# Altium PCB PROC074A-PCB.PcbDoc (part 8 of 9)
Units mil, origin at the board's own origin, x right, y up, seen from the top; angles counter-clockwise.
Board outline 2755.91 x 5300 mil, 10 copper layers (Top Layer, L2-GND, L3-SIG1, L4-GND, L5-PWR/SIG, L6-SIG2, L7-PWR2, L8-SIG3, L9-GND, Bottom Layer), stack 67.57 mil thick; 585 components, 490 nets, 2137 pads, 1150 vias.
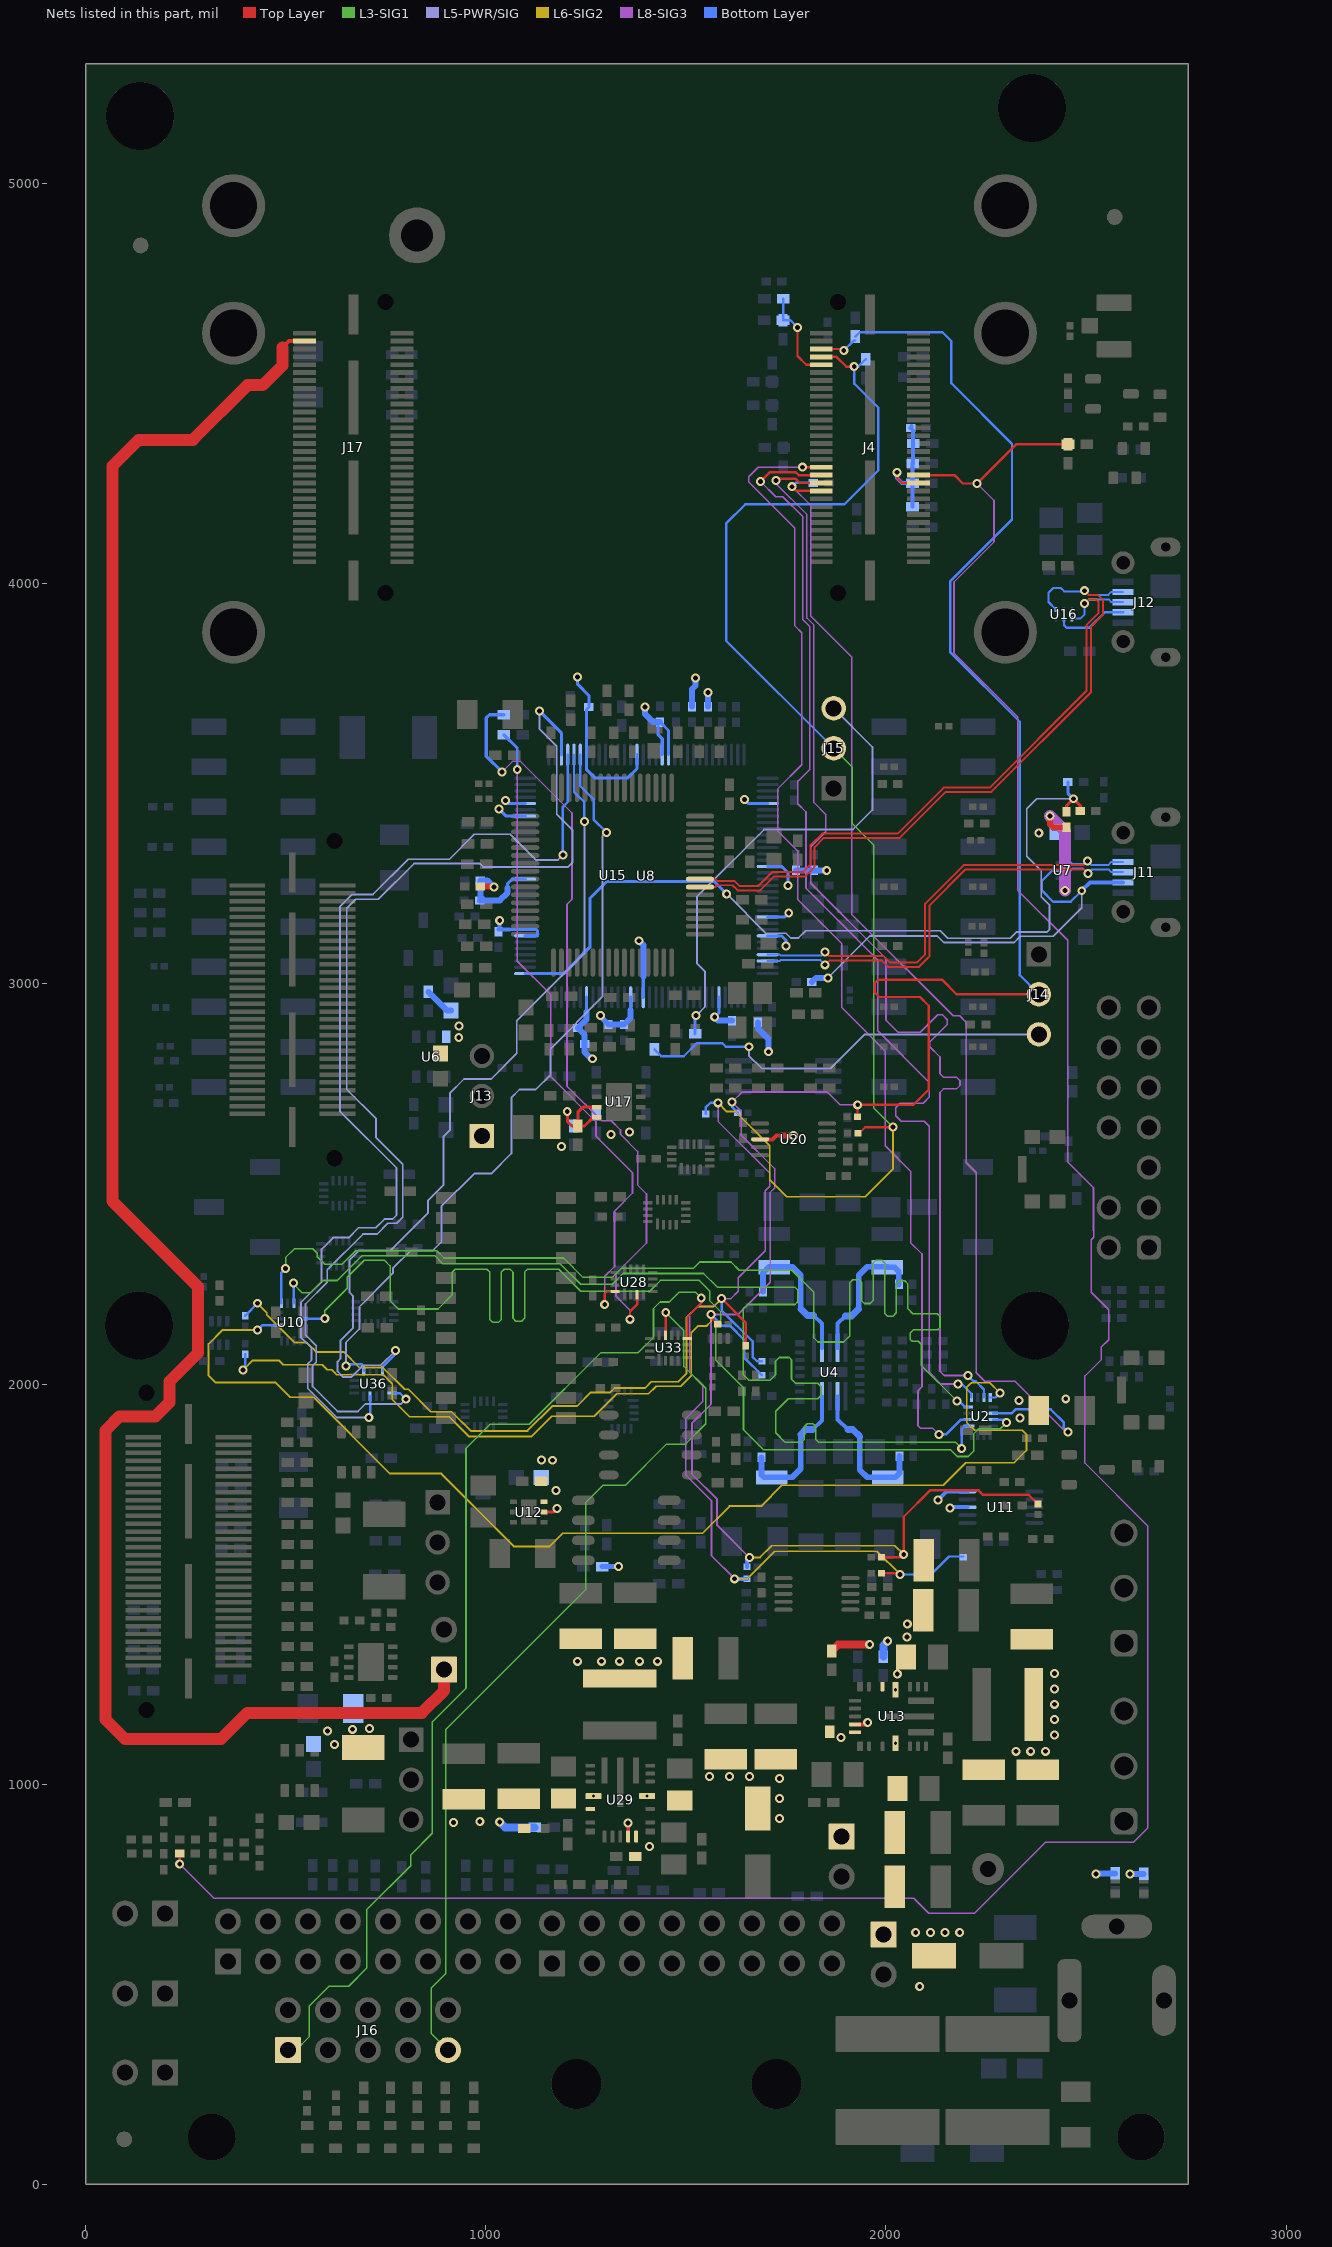
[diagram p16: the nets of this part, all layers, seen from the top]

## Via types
v1: diameter 22.4, hole 12.2, Top Layer to Bottom Layer, tented both sides, 1123 vias
v2: diameter 15.75, hole 7.87, Top Layer to Bottom Layer, tented both sides, 14 vias
v3: diameter 19.68, hole 7.87, Top Layer to Bottom Layer, tented both sides, 13 vias

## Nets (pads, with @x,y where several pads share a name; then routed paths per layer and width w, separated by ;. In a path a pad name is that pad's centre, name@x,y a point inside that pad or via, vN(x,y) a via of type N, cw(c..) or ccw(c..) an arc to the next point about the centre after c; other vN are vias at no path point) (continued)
RADAR_SCL: J4.55 J14.2 R9.1 R100.2 R171.1 R173.1 R303.2 R304.2 R319.2 R320.2 R321.2 | length 7706.2
  Top Layer w6: v1(1562.62,2173.53) 1562.62,2166.43 R173.1@1579.68,2149.37 ; J4.55@1838.5,4587.15 1890.48,4587.15 v1(1894.63,4583) ; R304.2@1928.9,2668.35 1928.9,2697.58 v1(1929.37,2698.06) 2068.87,2698.06 2106.89,2736.08 2106.89,2945.64 2085.15,2967.38 1983.39,2967.38 1971.82,2978.95 1971.82,3002.07 1980.61,3010.86 2140.02,3010.86 2176.82,2974.06 J14.2@2382.37,2974.06 ; R321.2@1989.09,1566.69 2037.01,1566.69 v1(2044.37,1574.06) 2044.37,1668.37 2110.28,1734.28 2231.72,1734.28 2243,1723 2357,1723 R303.2@2380,1700
  L6-SIG2 w4.5: v1(393.37,2035.06) 417.37,2059.06 482.37,2059.06 493.17,2048.26 590.74,2048.26 603.28,2035.72 615.17,2035.72 627.63,2023.26 743.74,2023.26 766.17,2000.82 766.17,1961.28 809.15,1918.3 908.35,1918.3 958.01,1868.64 1113.64,1868.64 1164.36,1919.36 1270.67,1919.36 1326.85,1975.54 1406.54,1975.54 1425.56,1994.56 1486.93,1994.56 1513.17,2020.8 1513.17,2128.42 1529.6,2144.86 1551.17,2144.86 1562.62,2156.31 v1(1562.62,2173.53) ; v1(1658.62,1566.53) 1684.85,1566.53 1714.37,1596.06 2022.37,1596.06 v1(2044.37,1574.06)
  L8-SIG3 w4: 1710.37,2254.09 1710.37,2478.52 1721.57,2489.72 1721.57,2538.78 1638.37,2621.98 1638.37,2681.9 v1(1615.37,2704.9) 1640.53,2730.06 1853.37,2730.06 1885.37,2698.06 v1(1929.37,2698.06)
  L8-SIG3 w4.5: v1(1658.62,1566.53) 1578,1647.16 1578,1712.08 1515,1775.08 1515,1902.38 1562.62,1950 v1(1562.62,2173.53) 1629.81,2173.53 1710.37,2254.09
  Bottom Layer w6: v1(393.37,2035.06) 398.74,2040.43 R171.1@398.74,2074.67 ; v1(1562.62,2173.53) 1590.1,2146.06 1609.94,2146.06 1645.37,2110.63 1645.37,2066.69 R100.2@1690.27,2021.8 ; v1(1615.37,2704.9) 1615.37,2692.06 R320.2@1629.38,2678.06 ; v1(1894.63,4583) 1920.01,4608.38 R9.1@1923.63,4608.38 ; R9.1@1923.63,4618.38 1934.45,4629.2 1934.8,4628.86 2141.14,4628.86 2163.5,4606.5 2163.5,4501.5 2315,4350 2315,4160.69 2160.37,4006.06 2160.37,3829.63 2334.4,3655.6 2334.4,3022.03 J14.2@2382.37,2974.06
  Bottom Layer w10: R319.2@1652.45,1543.27 1652.45,1560.36 v1(1658.62,1566.53)
RADAR_SDA: J4.53 J15.2 R13.1 R99.2 R174.2 R175.2 R305.2 R306.2 R322.2 R323.2 R324.2 | length 7466.5
  Top Layer w6: v1(1589.37,2213.59) 1650,2153 R175.2@1650,2095.98 ; J4.53@1838.5,4567.45 1876.18,4567.45 1900.63,4543 v1(1920.63,4543) ; R306.2@1930.08,2627.01 1933.32,2627.01 1948.37,2642.06 v1(2017.37,2642.06) ; R324.2@1989.09,1526.69 2032.73,1526.69 v1(2035.37,1524.06)
  L3-SIG1 w4: J15.2@1869.37,3589.06 1915.92,3542.51 1915.92,3400.9 1969.44,3347.38 1969.44,2689.99 v1(2017.37,2642.06)
  L6-SIG2 w4.5: v1(429,2202) 452.46,2178.54 452.46,2173.46 522.4,2103.52 552.37,2103.52 575.57,2080.32 644.84,2080.32 683.8,2041.36 742.61,2041.36 797.1,1986.86 806.62,1986.86 862.54,1930.94 914.02,1930.94 962.1,1882.86 1103.86,1882.86 1166,1945 1227.8,1945 1262.04,1979.24 1310.84,1979.24 1321.7,1990.1 1397.95,1990.1 1413.35,2005.5 1480.87,2005.5 1501.17,2025.8 1501.17,2165.42 1529.48,2193.73 1569.47,2193.73 v1@1589.33,2213.59 ; v1(1580.37,2703.06) 1602.43,2681 1623.96,2681 1709.57,2595.39 1709.57,2510.29 1751.8,2468.06 1948.37,2468.06 2017.37,2537.06 v1(2017.37,2642.06) ; v1(1621.89,1513.27) 1653.58,1513.27 1722.37,1582.06 1977.37,1582.06 v1(2035.37,1524.06)
  L8-SIG3 w4: v1(1580.37,2703.06) 1580.37,2656.49 1709.57,2527.29 1709.57,2494.69 1698.37,2483.49 1698.37,2333.51 1630.78,2265.92 1630.78,2231.78 1612.59,2213.59 v1(1589.37,2213.59) 1569.47,2193.73 1529.48,2193.73 1509.17,2173.42 1509.17,2029.83 1542.14,1996.86 1542.14,1956.27 1499.17,1913.29 1499.17,1773 1564,1708.17 1564,1571.16 v1(1621.89,1513.27)
  Bottom Layer w6: R174.2@398.74,2170.65 398.74,2171.74 v1(429,2202) ; R323.2@1549.38,2675.06 1549.38,2691.06 1561.37,2703.06 v1(1580.37,2703.06) ; v1(1589.37,2213.59) 1589.37,2184.23 1666.77,2106.83 1666.77,2067.66 1677.63,2056.8 R99.2@1690.27,2056.8 ; J15.2@1869.37,3589.06 1600.37,3858.06 1600.37,4150.62 1648.5,4198.75 1895.89,4198.75 1980.57,4283.43 1980.57,4440.6 1920.63,4500.54 v1(1920.63,4543) 1930.63,4543 R13.1@1949.63,4562 ; v1(2035.37,1524.06) 2112.38,1524.06 2157.38,1569.06 R305.2@2193.46,1569.06
  Bottom Layer w10: v1(1621.89,1513.27) R322.2@1652.45,1513.27
RADAR_SPI_CLK1: J4.21 U2.7 | length 2939
  Top Layer w6: v1(1725.06,4258.52) 1729.68,4263.15 1773.74,4263.15 1784.64,4252.25 J4.21@1838.5,4252.25
  L8-SIG3 w4: v1(1725.06,4258.52) 1725.06,4250.62 1802.47,4173.21 1802.47,3914.87 1820,3897.34 1820,3453.43 1849.57,3423.86 1849.57,3380.26 1812.05,3342.74 1812.05,3251.91 2000.14,3063.82 2000.14,2909.16 2030.25,2879.05 2085.4,2879.05 2129.15,2922.79 2141.17,2922.79 2153.19,2910.77 2153.19,2898.75 2109.44,2855 2109.44,2842.98 2135,2817.43 2135,2781.2 2135,2775.4 2143.7,2766.7 2176.3,2766.7 2185,2758 2185,2746.4 2176.3,2737.7 2143.7,2737.7 2135,2729 2135,2721.9 2135,2032 2145.74,2021.26 2204.73,2021.26 v1(2204.86,2021.39)
  Bottom Layer w6: v1(2204.86,2021.39) 2219.19,2007.06 2224.32,2007.06 2245.03,1986.35 U2.7@2245.03,1966.36
RADAR_SPI_CS1: J4.19 R249.1 U2.10 | length 3061.9
  Top Layer w6: v1(1765.37,4242.95) v1@1769.19,4242.95 ; v1@1769.19,4240.53 1777.17,4232.55 J4.19@1838.5,4232.55
  L8-SIG3 w4: v1(1765.37,4242.95) 1812.47,4195.86 1812.47,3919.01 1915,3816.48 1915,3173.27 2167.96,2920.31 2184.65,2920.31 2201,2903.96 2201,2552.83 2226,2527.83 2226,2028 2246.9,2007.1 2322.63,2007.1 2449.73,1880 v1(2455,1880)
  Bottom Layer w6: v1(1765.37,4242.95) 1774.76,4252.35 R249.1@1818.82,4252.35 ; U2.10@2268.65,1926.99 2269.12,1926.51 2313.41,1926.51 2323.7,1936.8 2411.76,1936.8 2444.71,1903.86 2444.71,1890.29 v1(2455,1880)
RADAR_SPI_MISO1: J4.25 U2.2 | length 2946
  Top Layer w6: v1(1791.78,4291.65) J4.25@1838.5,4291.65
  L8-SIG3 w4: v1(1791.78,4291.65) 1680.67,4291.65 1657.17,4268.15 1657.17,4254.58 1772.47,4139.28 1772.47,3894.93 1789.57,3877.83 1789.57,3548 1730,3488.43 1730,3381.43 1780,3331.43 1780,3210.86 1890,3100.86 1890,2940.43 1998.17,2832.26 1998.17,2595.4 2061.57,2532 2061.57,2353.43 2090,2325 2090,1993.06 2080,1983.06 2080,1896.06 2087,1889.06 2117.32,1889.06 v1(2132.22,1874.16)
  Bottom Layer w6: v1(2132.22,1874.16) 2150.09,1874.16 2187.17,1911.24 U2.2@2205.66,1911.24
RADAR_SPI_MOSI1: J4.23 U2.5 | length 2875.2
  Top Layer w6: v1(1686.37,4256.06) 1709.04,4278.72 1775.14,4278.72 1782.41,4271.45 1838,4271.45 J4.23@1838.5,4271.95
  L8-SIG3 w4: v1(1686.37,4256.06) 1724.43,4218 1742,4218 1792.47,4167.53 1792.47,3910.73 1810,3893.2 1810,3536.57 1779.8,3506.37 1779.8,3450.25 1800.05,3430 1800.05,3239.09 1979.37,3059.77 1979.37,2883.06 2108.57,2753.86 2108.57,2717.57 2093,2702 2035.8,2702 2024.6,2690.8 2024.6,2670.7 2038.3,2657 2096,2657 2108.57,2644.43 2108.57,2029.23 2137.8,2000 v1(2180,2000)
  Bottom Layer w6: v1(2180,2000) 2189.43,2000 2213.53,1975.89 U2.5@2213.53,1966.36
RADAR_SYNC_IN: J4.22 R248.2 R281.1 R283.1 R346.1 R348.1 | length 338.6
  Top Layer w6: v1(2027.63,4279) 2027.63,4265 2040.38,4252.25 J4.22@2081.5,4252.25
  Bottom Layer w10: v1(2027.63,4279) 2027.63,4265 2040.43,4252.2 R348.1@2066.38,4252.2 ; R248.2@2061.82,4390.15 R248.2@2064.01,4387.96 ; R248.2@2064.01,4394.99 R248.2@2064.01,4387.96 ; R346.1@2066.38,4193.05 R348.1@2066.38,4251.03 R348.1@2066.38,4252.2 ; R248.2@2064.01,4387.96 2068.01,4383.96 R283.1@2068.01,4351 2067.01,4350 R281.1@2067.01,4301 2066.38,4300.38 R348.1@2066.38,4252.2
RADAR_SYNC_OUT_SOP1: J4.24 R137.1 R350.1 R351.1 | length 6682.1
  Top Layer w6: v1(234.68,800.45) R137.1@234.68,826.26 ; J4.24@2081.5,4271.95 2170.91,4271.95 2191.8,4251.06 v1(2227.37,4251.06) 2325.18,4348.87 R350.1@2455.01,4348.87
  L8-SIG3 w4: v1(234.68,800.45) 320.34,714.79 2069.21,714.79 2107,677 2221.4,677 2399.46,855.06 2619.13,855.06 2654,889.92 2654,1646 2497.36,1802.64 2497.36,2020 2537.69,2060.33 2537.69,2091.68 2556.74,2110.73 2556.74,2185.97 2513.1,2229.61 2513.1,2360.95 2519.2,2367.05 2519.2,2382.95 2518.88,2383.27 2518.88,2490.49 2454.37,2555 2454.37,3109.18 2328.96,3234.59 2328.96,3667.61 2170,3826.57 2170,4005 2270,4105 2270,4208.43 v1(2227.37,4251.06)
RADAR_WARMRST: J4.51 R275.1 R357.1 R358.1 | length 238.2
  Top Layer w6: v1(1779,4641) 1779,4569.63 1800.88,4547.75 J4.51@1838.5,4547.75
  Bottom Layer w6: R275.1@1743.63,4712.99 1743.63,4659.99 R357.1@1742.63,4658.99 1761.01,4658.99 v1(1779,4641)
SPI_CLK1: U2.8 U10.2 | length 3009.5
  L6-SIG2 w4.5: v1(429.47,2135.26) 342.26,2135.26 307,2100 307,2021 324,2004 473.86,2004 510.86,1967 569.46,1967 760.4,1776.06 888.94,1776.06 1071.34,1593.66 1158.31,1593.66 1191.71,1627.06 1541.37,1627.06 1609.31,1695 1687.78,1695 1740.04,1747.26 2143.11,1747.26 2198.96,1803.11 2320.11,1803.11 2350.94,1833.94 2350.94,1874.06 2340.59,1884.41 2221.45,1884.41 2202,1903.86 2202,1992 2211.94,2001.94 2212.91,2001.94 2214.03,2003.06 2259.64,2003.06 v1(2285,1977.7)
  Bottom Layer w6: v1(429.47,2135.26) 441.39,2147.18 U10.2@480.87,2147.18 ; U2.8@2260.78,1966.36 2273.66,1966.36 v1(2285,1977.7)
SPI_CS1: U2.11 U10.10 | length 2988.6
  L3-SIG1 w4: v1(597.37,2164.06) 597.37,2183.38 653.37,2239.38 653.37,2266.62 695.89,2309.15 746.49,2309.15 760.48,2295.16 760.48,2207.96 780.78,2187.66 880.45,2187.66 916.12,2223.33 916.12,2279.77 923.41,2287.06 1002.45,2287.06 1009.7,2279.81 1009.7,2161.31 1016.95,2154.06 1031.45,2154.06 1038.7,2161.31 1038.7,2279.81 1045.95,2287.06 1060.45,2287.06 1067.7,2279.81 1067.7,2164.21 1074.95,2156.96 1089.45,2156.96 1096.7,2164.21 1096.7,2279.81 1103.95,2287.06 1181.91,2287.06 1236.97,2232 1409.49,2232 1436.49,2259 1533,2259 1560,2232 1560,2207.8 1586.66,2181.14 1586.66,2159.19 1575,2147.53 1575,2059.41 1643.97,1990.44 1643.97,1885.72 1693.43,1836.26 2160.6,1836.26 2178,1818.86 2205.86,1818.86 2219,1832 2219,1875 2232,1888 2285.35,1888 v1(2301.21,1903.86)
  Bottom Layer w6: U10.10@543.87,2162.93 596.24,2162.93 v1(597.37,2164.06) ; U2.11@2268.65,1911.24 2293.82,1911.24 v1(2301.21,1903.86)
SPI_MISO1: U2.1 U10.7 | length 2892
  L3-SIG1 w4: v1(519,2253) 519,2249.85 541.05,2227.8 560.8,2227.8 591.8,2258.8 628.58,2258.8 690.92,2321.15 871.96,2321.15 892.29,2300.82 1185.41,2300.82 1236.91,2249.32 1315.71,2249.32 1342.64,2276.25 1544.12,2276.25 1578.03,2242.34 1772.17,2242.34 1779.56,2234.95 1779.56,2205.73 1772.63,2198.8 1654.18,2198.8 1643.37,2187.99 1643.37,2023.55 1656.94,2009.98 1710.49,2009.98 1723.8,2023.29 1723.8,2057.1 1732.96,2066.26 1758.66,2066.26 1763.95,2060.97 1763.95,2012.03 1774.17,2001.81 1829.46,2001.81 1836.86,1994.41 1836.86,1970.82 1829.45,1963.41 1755.49,1963.41 1724.37,1932.29 1724.37,1878.06 1748.37,1854.06 1788.62,1854.06 1795.87,1861.31 1795.87,1893.41 1803.12,1900.66 1817.62,1900.66 1824.87,1893.41 1824.87,1861.31 1832.12,1854.06 2174.37,1854.06 v1(2189.37,1839.06)
  Bottom Layer w6: v1(519,2253) 520.24,2251.76 U10.7@520.24,2202.3 ; v1(2189.37,1839.06) 2189.37,1887.06 2197.8,1895.49 U2.1@2207.63,1895.49
SPI_MOSI1: U2.4 U10.5 | length 2939.3
  L3-SIG1 w4: v1(499.37,2289.06) 499.37,2316.21 521.43,2338.27 567.32,2338.27 578.57,2327.02 578.57,2318.29 597,2299.86 641.11,2299.86 674.4,2333.15 877.33,2333.15 895.34,2315.14 1194.39,2315.14 1242.95,2266.58 1316.1,2266.58 1338.54,2289.02 1518.5,2289.02 1534.48,2305 1612.65,2305 1633.07,2284.58 1764.85,2284.58 1820,2229.43 1820,2115 1830,2105 1894.02,2105 1909.87,2120.85 1909.87,2253.77 1917.12,2261.02 1931.62,2261.02 1938.87,2253.77 1938.87,2208.51 1946.12,2201.26 1960.62,2201.26 1967.87,2208.51 1967.87,2302.68 1975.12,2309.93 1989.62,2309.93 1996.87,2302.68 1996.87,2176.5 2004.37,2169 2017,2169 2025.87,2177.87 2025.87,2250.65 2033.28,2258.06 2046.88,2258.06 2054.87,2250.07 2054.87,2188 2066.87,2176 2128.12,2176 2135,2169.12 2135,2141.26 2129.3,2135.56 2069.12,2135.56 2061,2127.43 2061,2111.49 2065.49,2107 2080.88,2107 2088.57,2099.31 2088.57,2046.32 v1(2177.37,1957.52)
  Bottom Layer w6: U10.5@488.75,2202.3 488.75,2278.43 v1(499.37,2289.06) ; v1(2177.37,1957.52) 2182.91,1957.52 2197.69,1942.74 U2.4@2205.66,1942.74
SPIB_CLK_HDR: J16.1 U33.8 | length 2642.5
  Top Layer w6: U33.8@1503.83,2113.87 1503.83,2168.09 1538.37,2202.62 v1(1538.37,2215.06)
  L3-SIG1 w4: J16.1@505,335 525,335 559,369 559,446.25 607.75,495 656.94,495 702.52,540.57 702.52,686.52 812,796 812,823.07 866.08,877.15 866.08,1155.19 950.34,1239.45 950.34,1839.25 1010.41,1899.32 1108.65,1899.32 1288.01,2078.68 1381.1,2078.68 1418.96,2116.54 1418.96,2188.59 1435.37,2205 1458.46,2205 1482.88,2229.43 1524,2229.43 v1(1538.37,2215.06)
SPIB_CS_HDR: J16.9 U33.11 | length 2304.7
  Top Layer w6: U33.11@1448.72,2121.74 1449.57,2122.59 v1(1449.57,2178.86)
  L3-SIG1 w4: J16.9@905,335 863.57,376.43 863.57,490.54 900.17,527.14 900.17,1137.13 1250,1486.96 1250,1704.31 1292.83,1747.14 1348.77,1747.14 1451.63,1850 1499.17,1850 1549.65,1900.48 1549.65,1989.35 1495.02,2043.98 1495.02,2133.4 v1(1449.57,2178.86)
SW0: L1.1 R101.2 U4.10 | length 369.2
  Bottom Layer w10: 1819.37,2171.57 1839.97,2150.98 U4.10@1839.97,2090.73
  Bottom Layer w14.5: R101.2@1692.69,2230.56 1692.69,2277.55 1708.53,2293.38 1765.99,2293.38 1787.2,2272.17 1787.2,2188.23 1787.97,2187.46
  Bottom Layer w17: 1787.97,2187.46 1803.85,2171.57 1819.37,2171.57
SW1: L2.1 R102.2 U4.12 | length 359.7
  Bottom Layer w10: U4.12@1879.34,2090.73 1879.34,2150.98 1898.41,2170.06
  Bottom Layer w14.5: 1931.33,2187.02 1932.1,2187.79 1932.1,2272.18 1953.31,2293.39 L2.1@2004.65,2293.39 ; L2.1@2003.22,2292.12 2021.56,2292.12 2032.22,2281.46 R102.2@2032.22,2249.15
  Bottom Layer w17: 1898.41,2170.06 1914.37,2170.06 1931.33,2187.02
SW2: L3.1 R103.2 U4.25 | length 367
  Bottom Layer w10: 1816.87,1886.11 1839.97,1909.21 U4.25@1839.97,1969.47
  Bottom Layer w14.5: R103.2@1689.22,1816.78 1689.22,1772.46 1694.88,1766.8 L3.1@1714.65,1766.8 1765.99,1766.8 1787.2,1788.01 1787.2,1873.89
  Bottom Layer w17: 1787.2,1873.89 1799.42,1886.11 1816.87,1886.11
SW3: L4.1 R104.2 U4.23 | length 368
  Bottom Layer w10: U4.23@1879.34,1969.47 1879.34,1911.73 1904.96,1886.11
  Bottom Layer w14.5: 1934.72,1868.35 1934.72,1785.39 1953.31,1766.8 L4.1@2004.22,1766.8 2023.56,1766.8 2034.22,1777.46 2034.22,1805.46
  Bottom Layer w15: 2034.22,1805.46 R104.2@2034.22,1819.77
  Bottom Layer w17: 1904.96,1886.11 1916.96,1886.11 1934.72,1868.35
UNREG_IN1: C79.1 C80.1 C81.1 C82.1 C83.1 C84.1 C85.1 P3.1 R271.2 R403.2 U13.4 U13.14 U13.15 | length 145.7
  Top Layer w20: R271.2@1864.37,1332.68 1880.75,1349.06 v1(1959.37,1349.06)
  Bottom Layer w20: R403.2@1993.37,1318.68 1993.37,1347.06 v1(2004.37,1358.06)
  other v1: 2084.37,494.06 2074.37,629.06 2111.04,629.06 2147.7,629.06 2184.37,629.06 2028.37,1275.06 2052.56,1367.53 2053.37,1400.06
  other v2: 2023.94,1102.13 2023.94,1235.99
UNREG_IN2: C97.1 C98.1 C99.1 C100.1 C101.1 C102.1 C103.1 P7.1 R309.2 R315.2 U29.4 U29.14 U29.15 | length 92.6
  Bottom Layer w20: v1(1034.55,905.05) 1047.55,892.06 R309.2@1121.75,892.06
  other v1: 919.37,904.06 984.79,906.56 1734.37,914.06 1734.37,964.06 1734.37,1014.06 1559.37,1019.06 1609.37,1019.06 1659.37,1019.06
  other v2: 1269,970.2 1402.85,970.2
USBDM: J12.2 U15.7 U16.4 | length 1769.9
  Top Layer w4.99: U15.7@1535.19,3242.43 1573.13,3242.43 1577.47,3246.77 1616.44,3246.77 1629.21,3234 1686,3234 1721,3269 1798,3269 1822,3293 1822,3342 1845,3365 2034,3365 2149,3480 2263.56,3480 2512.56,3729 2512.56,3893 2542,3922.44 2542,3960.06 2529.56,3972.5 2506.5,3972.5 v1(2496,3983)
  Bottom Layer w4.99: U16.4@2425.32,3935.81 2406.3,3954.83 2406.3,3978.16 2417.84,3989.7 2437.3,3989.7 2445.64,3981.36 2494.36,3981.36 v1(2496,3983) 2506.5,3972.5 2556.13,3972.5 2563.61,3979.99 J12.2@2592.69,3979.99
USBDP: J12.3 U15.8 U16.1 | length 1647.9
  Top Layer w4.99: U15.8@1535.19,3262.11 1573.13,3262.11 1577.47,3257.77 1621,3257.77 1633.77,3245 1681.44,3245 1716.44,3280 1793.44,3280 1811,3297.56 1811,3346.56 1840.44,3376 2029.44,3376 2144.44,3491 2259,3491 2501.56,3733.56 2501.56,3897.56 2508,3904 2531,3927 2531,3955.5 2525,3961.5 2506.5,3961.5 v1(2496,3951)
  Bottom Layer w4.99: U16.1@2464.69,3913.17 2486.17,3913.17 2496,3923 v1(2496,3951) 2506.5,3961.5 2556.51,3961.5 2563.61,3954.39 J12.3@2592.69,3954.39
USBID: J12.4 U16.2 | length 181.8
  Bottom Layer w6: U16.2@2445,3912.19 2445,3897 2452,3890 2507.91,3890 2546.71,3928.8 J12.4@2592.69,3928.8
VBOOST_5V: C76.1 C77.1 R32.1 U12.2 U12.3 | length 76.7
  Top Layer w7.8: U12.2@1145.37,1680.06 1168.37,1680.06 v1(1177.37,1689.06)
  Bottom Layer w12: R32.1@1290.43,1543.78 v1(1331.38,1543.78)
  other v1: 1175,1734 1166.62,1809.53 1138.62,1810.53
VBUS_1_DETECT: C42.2 R152.1 R155.2 U8.1 | length 2139
  Top Layer w7: C42.2@2489.68,3431.59 C42.2@2489.68,3432.34
  Top Layer w7.8: R152.1@2451.11,3430.56 2451.11,3445.33 v1(2468.78,3463) 2485.53,3446.25 C42.2@2485.53,3432.34
  L5-PWR/SIG w4.5: v1(1602,3225) 1700,3127 1750.16,3127 1762.26,3114.9 1781.08,3114.9 1799.18,3133 2135.47,3133 2154.34,3114.13 2310.69,3114.13 2326.11,3129.55 2402.14,3129.55 2409,3136.41 2409,3197 2388,3218 2388,3283 2352,3319 2352,3438 2377,3463 v1(2468.78,3463)
  Bottom Layer w7.8: U8.1@1098.19,3025.89 1194.31,3025.89 1260,3091.58 1260,3213.63 1302.37,3256 1571,3256 v1(1602,3225) ; R155.2@2454.68,3505.06 2454.68,3477.09 v1(2468.78,3463)
VCC_3V3: C86.1 C89.1 C90.1 C91.1 L8.2 R291.1 R293.2 U11.8 U11.10 U13.21 U13.22 U20.8 | length 283
  Top Layer w9.8: U20.8@1685.43,2611.69 1716.69,2611.69 1726,2621 1739,2621
  Top Layer w10: U13.21@1922.56,1149.37 1949.68,1149.37 v1(1954.37,1154.06)
  Top Layer w15: 1739,2621 v1(1769,2621)
  Bottom Layer w10: v1(2130,1710) 2151.43,1731.43 U11.10@2203.71,1731.43 ; v1(2160,1690) 2162.06,1692.06 U11.8@2203.71,1692.06
  Bottom Layer w15: v1(2610,775) 2610.68,775.68 R293.2@2644.37,775.68
  other v1: 2325.37,1082.06 2361.87,1082.06 2398.37,1082.06 1887.37,1116.06 2421.37,1123.06 2421.37,1161.31 2421.37,1199.56 2421.37,1237.81 2421.37,1276.06 2335,1915 2332.6,1959.11 2449.37,1963.17
VCC_XDS_3V3: C29.1 C32.2 C34.2 C35.2 C36.2 C37.2 C38.2 R147.2 R148.1 R165.2 R166.2 R167.2 R168.2 R169.2 U6.6 U8.7 U8.8 U8.16 U8.26 U8.28 U8.39 U8.47 U8.51 U8.52 U8.69 U8.79 U8.90 U8.101 U8.113 U8.122 | length 2060.1
  Top Layer w15: C36.2@986.49,3243.99 1018.01,3243.99 v1(1020,3242)
  Bottom Layer w7: 1059.37,3136.13 U8.8@1098.19,3136.13
  Bottom Layer w7.8: U8.51@1440.71,3573.13 1440.71,3613.29 1430,3624 1430,3648.99 C35.2@1435.49,3654.48 1456.45,3633.51 U8.52@1456.45,3573.13 ; v1(1572,2917) 1582.44,2927.44 U8.101@1582.44,2966.84 ; v1(1646,3461) 1655.91,3451.09 U8.69@1704.49,3451.09 ; U8.90@1704.49,3120.38 1739.05,3120.38 1750,3109.43 v1(1750,3095) ; U8.79@1704.49,3293.61 1739.39,3293.61 1755,3278 v1(1755,3246)
  Bottom Layer w8: v1(1033,3437) 1050.41,3419.59 U8.26@1098.19,3419.59 ; v1(1049.37,3459.06) 1057.34,3451.09 U8.28@1098.19,3451.09 ; 1054.37,3239.71 1054.37,3251.06 1065.43,3262.11 U8.16@1098.19,3262.11 ; U8.7@1098.19,3120.38 1128.69,3120.38 1128.69,3133.69 1126.26,3136.13 U8.8@1098.19,3136.13 ; v1(1229.37,3767.06) 1229.37,3749.06 1257.68,3720.74 C34.2@1257.68,3692.06 1251.73,3686.1 U8.39@1251.73,3573.13 1251.73,3535.7 1272.37,3515.06 1354.37,3515.06 1377.71,3538.4 U8.47@1377.71,3573.13 ; 1251.73,2929.39 U8.122@1251.73,2966.84 ; U8.113@1393.46,2966.84 1393.46,3019.06
  Bottom Layer w10: v1(1034.55,3159) 1034.55,3138.92 1031.76,3136.13 1059.37,3136.13
  Bottom Layer w15: R148.1@856.1,2980.43 903.02,2933.5 C29.1@912.37,2933.5 ; R169.2@984.69,3209 R169.2@986.49,3209 ; v1(1020,3242) 1003.01,3258.99 R168.2@986.49,3258.99 R169.2@986.49,3209 ; 1054.37,3239.71 1054.37,3228.37 1035,3209 R169.2@986.49,3209 ; 1251.73,2929.39 1251.73,2911.73 C38.2@1230.06,2890.06 1247.06,2873.06 R167.2@1247.06,2850.06 1247.06,2829.37 1263.37,2813.06 v1(1266.37,2813.06) ; v1(1382.37,3108.06) 1393.46,3096.96 1393.46,3019.06 ; v1(1397.37,3692.59) 1397.37,3675.06 1417.95,3654.48 C35.2@1435.49,3654.48 ; R166.2@1515.49,3693.45 1515.49,3737.17 1524.37,3746.06 v1(1524.37,3765.06) ; R165.2@1555.49,3693.45 v1(1555.49,3728.49) v1@1556,3729 ; v1(1572,2917) 1580.55,2908.45 C32.2@1615.49,2908.45
  other v1: 932.2,2866.15 933.02,2895
VDDC_1: C33.2 C39.2 C40.2 C41.2 U8.87 U8.115 | length 277.4
  Bottom Layer w7.8: U8.87@1704.49,3167.62 1747.62,3167.62 v1(1757,3177)
  Bottom Layer w8: 1361.97,2934.72 U8.115@1361.97,2966.84
  Bottom Layer w15: v1(1286.37,2921.06) 1286.37,2918.74 C33.2@1306.37,2898.74 C41.2@1345.37,2898.74 1361.97,2915.34 1361.97,2934.72 ; C40.2@1775.49,3284.08 C39.2@1820.49,3284.08 v1(1851.92,3284.08)
VLDO_3V3: C64.1 C65.1 J13.1 R221.1 R222.2 U17.3 U17.4 | length 198.7
  Top Layer w8: v1@1203.73,2680.7 1203.73,2656.18 1214.9,2645 C65.1@1230,2645 ; U17.4@1277.24,2666.61 1268.06,2666.61 1246.44,2645 C65.1@1230,2645 ; U17.3@1277.24,2692.2 1242.52,2692.2 1230,2679.69 C65.1@1230,2645
  other v1: 1189.37,2594.06 1312.37,2624.06 1359.37,2630.06 1203.37,2681.06
VPP_1P7: J17.4 P1.1 | length 4974.8
  Top Layer w10: 491.93,4590.57 491.93,4591.27 507.6,4606.95 J17.4@547,4606.95
  Top Layer w30: 491.93,4590.57 491.93,4546.5 442.13,4496.7 404.21,4496.7 267.51,4360 132,4360 66.37,4294.37 66.37,2457.63 280.1,2243.9 280.1,2077.01 209,2005.91 209,1954 174,1919 84,1919 49.42,1884.42 49.42,1161 97.37,1113.06 338.37,1113.06 403.57,1178.26 840.14,1178.26 895.63,1233.75 P1.1@895.63,1286
WIDE_IN_5V_OP: C31.1 C104.1 C105.1 C106.1 C107.1 L9.2 R49.1 R115.1 R313.2 R329.2 U29.21 U29.22 | length 82.5
  Top Layer w8: U29.21@1355.61,868.82 v1(1355.61,902.82)
  Bottom Layer w15: v1(2525,775) 2526.83,776.83 R313.2@2572.7,776.83
  other v1: 1409.37,844.06 621.37,1099.06 603.73,1133.11 666.37,1137.06 709.37,1139.06 1229.37,1307.06 1289.37,1307.06 1334.37,1307.06 1384.37,1307.06 1429.37,1307.06
XDS_I2C_SCL: J14.3 R48.1 | length 1056.1
  L5-PWR/SIG w4.5: v1(1657.37,2843.06) 1657.37,2821.03 1689.54,2788.86 1861.57,2788.86 1946.77,2874.06 J14.3@2382.37,2874.06
  Bottom Layer w6: R48.1@1421.37,2836.43 1438.55,2819.26 1494.57,2819.26 1527.37,2852.06 1590.91,2852.06 1599.91,2843.06 v1(1657.37,2843.06)
XDS_I2C_SDA: J15.3 R47.1 | length 1185
  L5-PWR/SIG w4.5: v1(1525.37,2921.06) 1548,2943.69 1548,3030.91 1527.37,3051.54 1527.37,3218.06 1695.37,3386.06 1917.37,3386.06 1966.37,3435.06 1966.37,3592.06 J15.3@1869.37,3689.06
  Bottom Layer w8: R47.1@1522.99,2875.06 1522.99,2918.68 v1(1525.37,2921.06)
XDS_RS232RX: R160.1 U28.3 | length 1919.9
  Top Layer w6: v1(1360.21,2161.9) 1360.21,2181.07 1377.87,2198.73 U28.3@1377.87,2223.5
  L8-SIG3 w4: v1(1040.37,3530.06) 1066.57,3556.26 1086.74,3556.26 1215.37,3427.62 1215.37,3211.63 1202.8,3199.06 1202.8,2744.6 1289.34,2658.06 1313.37,2658.06 1336.37,2635.06 1336.37,2624.06 1379.17,2581.26 1379.17,2497.4 1401.57,2475 1401.57,2352.66 1325.22,2276.31 1325.22,2219.33 1360.21,2184.34 v1(1360.21,2161.9)
  Bottom Layer w8: v1(1040.37,3530.06) 1001,3569.43 1001,3665 1009.06,3673.06 R160.1@1044.75,3673.06
XDS_RS232TX: R157.1 U28.16 | length 1640.9
  Top Layer w6: v1(1297,2199) 1297,2225.61 1302.77,2231.38 U28.16@1322.76,2231.38
  L8-SIG3 w4: v1(1078.37,3536.06) 1078.37,3057.06 1161.8,2973.63 1161.8,2768.63 1275.37,2655.06 1275.37,2619.49 1366.57,2528.29 1366.57,2477.26 1321.39,2432.08 1321.39,2293.78 1297,2269.39 v1(1297,2199)
  Bottom Layer w7: R157.1@1044.75,3623.06 1078.37,3589.43 v1(1078.37,3536.06)
XDSET_1_DM: J11.2 U7.4 U8.93 | length 1144.9
  Top Layer w4.99: v1(1848,3080) 1858.5,3069.5 1994.46,3069.5 2009.96,3054 2078,3054 2098,3074 2098,3201 2194.19,3297.19 2493.51,3297.19 v1(2503.37,3307.06)
  Bottom Layer w4.99: U8.93@1704.49,3073.13 1734.54,3073.13 1736.92,3070.76 1838.76,3070.76 v1(1848,3080) ; U7.4@2453.81,3303.69 2462.22,3303.69 2466.56,3299.34 2495.66,3299.34 v1(2503.37,3307.06) 2513.23,3297.19 2555.82,3297.19 2563.61,3304.99 J11.2@2592.69,3304.99
XDSET_1_DP: J11.3 U7.5 U8.94 | length 1149
  Top Layer w4.99: v1(1848,3048) 1858.5,3058.5 1989.91,3058.5 2005.41,3043 2082.56,3043 2105.78,3066.22 2109,3069.44 2109,3196.44 2198.75,3286.19 2495.25,3286.19 v1(2505.11,3276.33)
  Bottom Layer w4.99: U8.94@1704.49,3057.39 1734.54,3057.39 1736.92,3059.76 1836.24,3059.76 v1(1848,3048) ; U7.5@2453.81,3284 2462.22,3284 2466.56,3288.34 2493.1,3288.34 v1(2505.11,3276.33) 2514.97,3286.19 2556.81,3286.19 2563.61,3279.39 J11.3@2592.69,3279.39
XDSET_1_ID: J11.4 R158.2 U7.2 | length 1118
  L5-PWR/SIG w4.5: v1(1855,3015) 1960,3120 2127.89,3120 2144.26,3103.63 2320.69,3103.63 2336.11,3119.05 2417.66,3119.05 2489.37,3190.76 v1(2489.37,3233.06)
  Bottom Layer w6: U7.2@2430.19,3284 2415.53,3284 2389.7,3258.17 2389.7,3233.6 2417.9,3205.4 2461.71,3205.4 v1(2489.37,3233.06)
  Bottom Layer w10: v1(2489.37,3233.06) 2510.12,3253.8 J11.4@2592.69,3253.8
  Bottom Layer w15: R158.2@1814.69,3005 1824.69,3015 v1(1855,3015)
XDSET_1_VBUS: R152.2 R154.2 R159.2 U7.6 | length 383.1
  Top Layer w15: v1(2410.15,3419.56) 2410.15,3398.85 2417.81,3391.19 R152.2@2451.11,3391.19
  L8-SIG3 w30: v1(2410.15,3419.56) 2448,3381.7 v1(2448,3234)
  Bottom Layer w7.8: v1(2448,3234) 2453.81,3239.81 U7.6@2453.81,3264.31
  Bottom Layer w15: R159.2@1680.49,2904.08 1680.49,2888.27 1706.82,2861.94 v1(1706.82,2830.66)
  other v1: 2382,3377
XDSET_TCK: U8.35 U36.16 | length 2877.9
  L5-PWR/SIG w4.5: v1(799.96,1962.11) 788.31,1950.46 699.14,1950.46 680.05,1931.37 629.49,1931.37 567,1993.86 567,2045.93 576.07,2055 576.07,2095.89 549.05,2122.91 549.05,2200.03 603.37,2254.35 603.37,2285.37 693,2375 728.07,2375 754.91,2401.84 776.88,2401.84 792.38,2417.34 792.38,2548.95 725.52,2615.81 725.52,2662.76 652.15,2736.13 652.15,3189.07 675.08,3212 731.37,3212 820.37,3301 984.5,3301 993,3292.5 1205.5,3292.5 1217,3304 1217,3384.03 1177,3424.03 1177,3594 1134.37,3636.63 v1(1134.37,3682.06)
  Bottom Layer w6: U36.16@765.61,1977.43 784.64,1977.43 v1(799.96,1962.11)
  Bottom Layer w8: v1(1134.37,3682.06) 1188.74,3627.69 U8.35@1188.74,3573.13
XDSET_TDI: U8.38 U36.9 | length 1965.5
  L5-PWR/SIG w4.5: v1(650.37,2045.06) 650.37,2104.07 684.17,2137.87 684.17,2193.36 767.7,2276.89 767.7,2289.43 812,2333.73 867.36,2333.73 888.71,2355.08 888.71,2444.03 970.79,2526.11 1013.6,2526.11 1063.77,2576.28 1063.77,2716 1084.03,2736.26 1124.57,2736.26 1161.8,2773.49 1161.8,2838.27 1291.37,2967.84 1291.37,3369.06 v1(1301.37,3379.06)
  Bottom Layer w6: v1(650.37,2045.06) 654.37,2049.06 689.37,2049.06 694.75,2043.68 U36.9@694.75,2032.55 ; U8.38@1235.98,3573.13 1235.98,3495.06 1269.37,3461.67 1269.37,3411.06 v1(1301.37,3379.06)
XDSET_TDO: U8.37 U36.12 | length 2144.3
  L5-PWR/SIG w4.5: v1(774.37,2083.78) 737.62,2047.03 693.42,2047.03 663.85,2017.46 643.16,2017.46 629.3,2031.32 629.3,2056.25 636.3,2063.25 636.3,2107.9 667.72,2139.32 667.72,2220.44 659.37,2228.79 659.37,2310.32 683.05,2334 762.2,2334 855,2426.8 855,2458.16 893.91,2497.07 893.91,2618.54 910,2634.63 910,2727.22 945.36,2762.58 1013.37,2762.58 1077.31,2826.52 1077.31,2908 1246.37,3077.06 v1(1246.37,3406.06)
  Bottom Layer w6: U36.12@741.99,2032.55 741.99,2042.68 774.37,2075.06 v1(774.37,2083.78) ; U8.37@1220.23,3573.13 1220.23,3480.19 1246.37,3454.06 v1(1246.37,3406.06)
XDSET_TMS: U8.36 U36.3 | length 2594
  L5-PWR/SIG w4.5: v1(707.37,1916.06) 627.83,1916.06 555,1988.89 555,2050.9 564.07,2059.97 564.07,2090.92 537.66,2117.33 537.66,2203.83 589.37,2255.54 589.37,2337.37 618,2366 656.97,2366 681.51,2390.54 724.77,2390.54 746.85,2412.63 767.46,2412.63 776.68,2421.85 776.68,2540.31 635,2681.99 635,3193 666,3224 717.77,3224 805.77,3312 909,3312 971,3374 1061,3374 1125,3310 1180.31,3310 v1(1192.37,3322.06)
  Bottom Layer w6: v1(707.37,1916.06) 710.5,1919.18 U36.3@710.5,1969.56 ; v1(1192.37,3322.06) 1192.37,3442.62 1204.49,3454.74 U8.36@1204.49,3573.13
pads on no net: Designator1. FID1.1 FID2.1 FID3.1 FID4.1 FID5.1 FID6.1 J4.MH1 J4.MH2 J5.3 J5.6 J5.8 J5.10 J5.11 J5.12 J6.7 J6.20 J9.10 J9.11 J9.14 J9.18 J9.20 J9.22 J9.24 J9.26 J9.28 J9.30 J9.32 J9.34 J9.36 J9.38 J9.40 J9.42 J9.44 J9.46 J9.48 J9.50 J9.52 J9.53 J9.54 J9.55 J9.56 J9.59 J9.60 J9.MH1 J9.MH2 J10.4 J10.5 J10.6 J10.8 J10.14 J10.MH1 J10.MH2 J17.6 J17.8 J17.10 J17.12 J17.14 J17.16 J17.26 J17.28 J17.35 J17.37 J17.39 J17.41 J17.43 J17.44 J17.45 J17.46 J17.47 J17.48 J17.49 J17.50 J17.51 J17.52 J17.53 J17.54 J17.55 J17.56 J17.57 J17.58 J17.59 J17.60 J17.MH1 J17.MH2 J19.13 J19.14 LBL1.0 MH1. MH2. MH3. MH4. SW1.1 SW1.3 SW2.1 SW2.3 U4. U8.2 U8.3 U8.4 U8.5 U8.6 U8.11 U8.12 U8.13 U8.14 U8.15 U8.18 U8.19 U8.20 U8.21 U8.22 U8.23 U8.24 U8.27 U8.29 U8.30 U8.31 U8.32 U8.41 U8.42 U8.43 U8.44 U8.45 U8.46 U8.49 U8.50 U8.53 U8.54 U8.56 U8.57 U8.65 U8.67 U8.71 U8.72 U8.73 U8.74 U8.75 U8.76 U8.77 U8.78 U8.81 U8.82 U8.83 U8.84 U8.85 U8.86 U8.91 U8.92 U8.97 U8.98 U8.99 U8.100 U8.102 U8.103 U8.104 U8.105 U8.106 U8.107 U8.108 U8.109 U8.110 U8.116 U8.117 U8.118 U8.119 U8.120 U8.121 U8.123 U8.124 U8.125 U8.126 U8.127 U8.128 U9.3 U12.7@1106.98,1662.34 U12.7@1106.98,1697.77 U13.4A U13.4B U13.8A U13.8B U13.9A U13.9B U13.9C U13.9D U13.10A U13.10B U13.14A U13.14B U13.17 U14.6 U14.7 U15.21 U15.22 U15.23 U15.24 U15.29 U15.33 U15.40 U15.41 U15.48 U15.60 U17.7 U17.9@1332.36,2680.2 U17.9@1332.36,2729.8 U28.7 U28.8 U28.9 U28.10 U28.11 U28.12 U29.4A U29.4B U29.8A U29.8B U29.9A U29.9B U29.9C U29.9D U29.10A U29.10B U29.14A U29.14B U29.17 U30.7 U35.7 U35.8 U35.9 U35.10 U35.11 U35.12

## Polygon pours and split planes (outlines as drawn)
GND on Top Layer "NONET_L-01_P-001" (solid, remove dead copper, pour order 1048): 20 vertices, not listed, extent 68,3766 2387,5261
BP_LP_3V3 on Top Layer "Bottom Layer-No Net 1" (solid, remove dead copper, pour order 1038): 23 vertices, not listed, extent 695,3087.33 987.4,3730
MCU_3V3 on Top Layer "NONET_L-01_P-001" (solid, remove dead copper, pour order 886): 20 vertices, not listed, extent 205,3472 1153,3854.06
BRD_3V3 on Top Layer "Bottom Layer-No Net 1" (solid, remove dead copper, pour order 1034): 1029.06,2701.26 1025.85,2698.06 898.37,2698.06 889.57,2707.26 865.21,2731.62 865.21,2775.49 873.78,2784.06 920.37,2784.06 949.43,2755 1020.36,2755 1029.06,2746.3
VCC_XDS_3V3 on Top Layer "Bottom Layer-No Net 1" (solid, remove dead copper, pour order 1032): 947,2915 956.38,2905.62 956.38,2855 946.38,2845 920.97,2845 915,2839.03 915,2811 910.37,2806.37 855,2806.37 846.37,2815 846.37,2897.09 864.28,2915
GND on Top Layer "AVDD" (solid, pour order 808): 19 vertices, not listed, extent 1045.72,1640.53 1184.62,1828.53
VLDO_3V3 on Top Layer "NONET_L-01_P-001" (solid, remove dead copper, pour order 852): 22 vertices, not listed, extent 1134.37,2567.82 1384.37,2699.06
VCC_3V3 on Top Layer "net" (solid, remove dead copper, pour order 802): 1840.37,1143.06 1840.37,1101.06 1847.37,1094.06 1888.37,1094.06 1916.37,1122.06 1936.37,1122.06 1941.37,1127.06 1941.37,1134.06 1937.37,1138.06 1899.37,1138.06 1890.37,1147.06 1844.37,1147.06
GND on Top Layer "NONET_L-01_P-001" (solid, remove dead copper, pour order 804): 1589.37,719.05 1606.43,702 1732.31,702 1749.37,719.05 1749.37,824.05 1734.37,839.06 1604.37,839.05 1589.37,824.06
BRD_3V3 on Top Layer "VS" (solid, remove dead copper, pour order 806): 17 vertices, not listed, extent 1074,1495 1205,1618
FTDI_VBUS on Top Layer "VS" (solid, remove dead copper, pour order 812): 2501,4248 2514,4235 2514,4204 2448,4138 2355,4138 2335,4158 2335,4215 2368,4248
GND on Top Layer "net" (solid, remove dead copper, pour order 814): 17 vertices, not listed, extent 1786.37,970.06 1942.37,1198.06
NetC96_2 on Top Layer "NONET_L-01_P-001" (solid, remove dead copper, pour order 816): 19 vertices, not listed, extent 1234.37,939.06 1509.37,1191.06
WIDE_IN_5V_OP on Top Layer "NONET_L-01_P-001" (solid, remove dead copper, pour order 818): 1139.37,1350.79 1139.37,1188.8 1147.94,1180.23 1218.55,1180.23 1242.37,1204.06 1519.37,1204.06 1524.37,1209.06 1524.37,1365.31 1499.25,1390.42 1179,1390.42
UNREG_IN2 on Top Layer "NONET_L-01_P-001" (solid, remove dead copper, pour order 820): 25 vertices, not listed, extent 1379.37,833.48 1944.37,1090.24
GND on Top Layer "NONET_L-01_P-001" (solid, remove dead copper, pour order 822): 48 vertices, not listed, extent 889,994.06 1778,1512.02
VCC_3V3 on Top Layer "NONET_L-01_P-001" (solid, remove dead copper, pour order 824): 2318.55,1899.06 2318.55,1949.2 2307.35,1960.4 2307.35,1986.06 2307.97,1986.06 2320.97,1999.06 2433.89,1999.06 2460,1972.95 2460,1916.9 2429.52,1886.42 2331.8,1886.42 2319.16,1899.06
BRD_3V3 on Top Layer "NONET_L-01_P-001" (solid, remove dead copper, pour order 826): 2459.37,1896.27 2460,1896.89 2460,1977.79 2476.27,1994.06 2544.2,1994.06 2579.37,1958.89 2579.37,1925.81 2539.98,1886.42 2469.22,1886.42
GND on Top Layer "net" (solid, remove dead copper, pour order 828): 54 vertices, not listed, extent 2049.37,669.06 2530.71,1637.06
VPP_1P7 on Top Layer "NONET_L-01_P-001" (solid, remove dead copper, pour order 830): 494.38,4569.06 506.03,4569.06 509.14,4572.17 509.14,4595.94 512.26,4599.06 576.83,4599.06 577.1,4612.06 496.26,4612.06 475.37,4591.17 475.37,4573.05 479.37,4569.05
CB_PMIC_1V8 on Top Layer "NONET_L-01_P-001" (solid, remove dead copper, pour order 832): 1809.73,4128.02 1869.54,4128.2 1877,4120.74 1877,4092.6 1882.33,4087.27 1903.86,4087.27 1908.34,4091.75 1908.34,4134.59 1902.16,4140.77 1896.62,4140.77 1810.55,4140.77 1808.73,4138.96 1808.73,4129.01
CB_PMIC_1V2 on Top Layer "NONET_L-01_P-001" (solid, remove dead copper, pour order 834): 1793.63,4120.86 1765.82,4148.67 1737.26,4148.67 1730.69,4142.11 1730.65,4131.86 1730.65,4098.54 1741.27,4087.93 1866.42,4087.93 1867.11,4088.63 1867.11,4120.16 1866.39,4120.86
WIDE_IN_5V_OP on Top Layer "GND_L01_P-001" (solid, remove dead copper, pour order 836): 25 vertices, not listed, extent 1354.37,797.4 1429.37,884.06
GND on Top Layer "GND_L01_P-001" (solid, remove dead copper, pour order 838): 34 vertices, not listed, extent 1304.37,759.06 1509.37,884.06
UNREG_IN1 on Top Layer "NONET_L-01_P-001" (solid, remove dead copper, pour order 840): 21 vertices, not listed, extent 1947.37,1209.06 2124.37,1624.06
VCC_3V3 on Top Layer "net" (solid, remove dead copper, pour order 842): 2297.37,1104.06 2278.37,1085.06 2193.37,1085.06 2191.87,1082.56 2188.37,1079.06 2188.37,999.06 2208.37,979.06 2422.37,979.06 2448.37,1005.06 2448.37,1378.06 2426.37,1400.06 2316.37,1400.06 2297.37,1381.06
NetC78_2 on Top Layer "net" (solid, remove dead copper, pour order 844): 2204.37,1300.06 2263.37,1300.06 2289.37,1274.06 2289.37,1109.06 2274.37,1094.06 2149.37,1094.06 2132.72,1110.71 2132.72,1140.71 2112.37,1161.06 1994.37,1161.06 1994.37,1177.06 2122.37,1177.06 2172.72,1227.41 2172.73,1268.41
UNREG_IN1 on Top Layer "net" (solid, remove dead copper, pour order 846): 22 vertices, not listed, extent 1952.37,459.05 2209.37,1129.06
BRD_3V3 on Top Layer "NONET_L-01_P-001" (solid, remove dead copper, pour order 848): 761.87,4572.06 761.87,4543.79 762.87,4542.79 855.65,4542.79 878.36,4520.05 934.13,4520.06 952.37,4538.29 952.37,4620.06 937.37,4635.06 871.37,4635.05 850.37,4614.06 850.37,4591.06 831.37,4572.05
NetC119_1 on Top Layer "AVDD" (solid, pour order 850): 751.05,1437.62 751.05,1321.19 760.77,1311.47 834.84,1311.47 859.57,1336.2 926.62,1336.2 940.71,1350.29 940.71,1438.06 939.71,1439.06 936.21,1442.56 755.99,1442.56
WIDE_IN_5V_OP on Top Layer "AVDD" (solid, remove dead copper, pour order 858): 624.62,1119.53 624.62,1065.53 624.62,1059.53 633.62,1050.53 635.17,1048.99 698.04,1048.99 808.54,1048.99 820.09,1060.53 820.09,1108.48 820.08,1140.34 807.37,1153.05 635.37,1153.06 624.62,1142.31
5V_IN on Top Layer "AVDD" (solid, pour order 860): 17 vertices, not listed, extent 592.62,851.64 801.62,1013.53
NetJ12_6 on Top Layer "NONET_L-01_P-001" (solid, remove dead copper, pour order 862): 2556.37,3832.06 2607.37,3781.06 2726.37,3781.06 2739.37,3794.06 2739.37,3816.06 2739.37,4116.06 2727.37,4128.06 2587.37,4128.06 2556.37,4097.06
CB_PMIC_1V0 on Top Layer "NONET_L-01_P-001" (solid, remove dead copper, pour order 864): 1738.37,4077.06 1680.37,4019.06 1580.37,4019.06 1544.57,3983.26 1544.57,3918.86 1569.37,3894.06 1728.43,3894.06 1778.43,3944.06 1888.12,3944.06 1914.37,3970.3 1914.37,4041.06 1878.37,4077.06 1757.37,4077.06
NetF1_2 on Top Layer "net" (solid, remove dead copper, pour order 866): 2413.97,571.85 2431.18,589.06 2499.37,589.06 2529.37,559.06 2529.37,199.06 2519.37,189.06 2448.94,189.06 2413.97,224.02
NetD1_1 on Top Layer "net" (solid, remove dead copper, pour order 868): 2349.37,103.96 2349.37,49.06 2378.43,20 2530.31,20 2569.37,59.06 2569.37,179.69 2560,189.06 2434.47,189.06
GND on Top Layer "net" (solid, remove dead copper, pour order 870): 2399.37,139.06 2399.37,119.06 2371.8,91.49 2352.35,92.04 2280.31,20 1888.43,20 1849.37,59.06 1849.37,189.06 1869.37,209.06 2382.44,209.06 2405.35,186.14 2405.36,145.04
NetC22_1 on Top Layer "net" (solid, remove dead copper, pour order 872): 27 vertices, not listed, extent 1737.37,234.06 2424.37,809.06
GND on Top Layer "NONET_L-01_P-001" (solid, remove dead copper, pour order 874): 2224.37,619.06 2224.37,513.38 2238.69,499.06 2360.06,499.06 2380,519 2380,620.41 2356.35,644.06 2249.37,644.06
UNREG_IN2 on Top Layer "NONET_L-01_P-001" (solid, remove dead copper, pour order 880): 18 vertices, not listed, extent 889.37,875.77 1294.37,994.06
NetJ11_6 on Top Layer "NONET_L-01_P-001" (solid, remove dead copper, pour order 884): 2559.37,3424.05 2559.37,3138.06 2596.37,3101.06 2721.37,3101.06 2750.37,3130.06 2750.37,3430.06 2723.37,3457.06 2592.37,3457.06
NetJ17_1 on Top Layer "NONET_L-01_P-001" (solid, remove dead copper, pour order 888): 25 vertices, not listed, extent 505.38,4567.59 830.86,4807
FTDI_3V3 on Top Layer "NONET_L-01_P-001" (solid, remove dead copper, pour order 876): 1057.37,2666.94 1057.37,2536.26 1074.57,2519.06 1108.17,2519.06 1129.37,2540.26 1129.37,2664.86 1119.37,2674.86 1117.9,2673.38 1063.82,2673.38
BOOST_3V3_IN on Top Layer "AVDD" (solid, pour order 810): 17 vertices, not listed, extent 828.02,1698.39 1080,1840
BOOST_3V3_IN on Top Layer "Bottom Layer-No Net 1" (solid, remove dead copper, pour order 1042): 1071.93,1632.06 1071.93,1614.76 1061.63,1604.46 1061.63,1534.97 1015.71,1489.06 941.1,1489.06 936.21,1493.95 936.21,1615.53 952.73,1632.06 985,1632.06 988,1635.06 1068.93,1635.06
NetL7_1 on Top Layer "Bottom Layer-No Net 1" (solid, remove dead copper, pour order 1044): 1036.66,1651.66 1058.74,1673.74 1068.6,1673.74 1068.62,1673.75 1068.62,1683.1 1037.15,1683.1 1030.54,1689.71 940.65,1689.71 936.57,1685.63 936.57,1654.8 939.71,1651.66
VBOOST_5V on Top Layer "AVDD" (solid, pour order 856): 1185.53,1830 1190.63,1824.91 1190.62,1822.38 1190.62,1727.53 1190.63,1701.71 1190.63,1691.63 1179.29,1680.29 1145.61,1680.29 1145.37,1680.06 1140,1685.43 1140,1735.16 1128.31,1746.85 1125.29,1749.99 1125.29,1826.55 1128.75,1830
BRD_3V3 on Top Layer "NONET_L-01_P-001" (solid, remove dead copper, pour order 882): 2053.37,4069.06 2053.37,4100.06 2054.37,4101.06 2115.37,4101.06 2123.37,4109.06 2240.37,4109.06 2262.39,4087.05 2262.39,4017.06 2223.38,3978.05 2159.37,3978.06 2125.37,4012.06 2125.37,4060.06 2116.37,4069.06
5V_IN on Bottom Layer "M1 Board Outline-No Net" (solid, pour order 914): 28 vertices, not listed, extent 1719.96,1798.11 1825.96,2006.11
VCC_XDS_3V3 on Bottom Layer "Bottom Layer-No Net 1" (solid, remove dead copper, pour order 1028): 892.63,2953 939.17,2953 947.12,2945.06 947.12,2863.63 933.02,2849.53 892.93,2849.53 886.91,2855.55 886.91,2947.28
GND on Bottom Layer "NONET_L-01_P-001" (solid, remove dead copper, pour order 1014): 20 vertices, not listed, extent 68,3766 2387,5261
NetC22_1 on Bottom Layer "net" (solid, remove dead copper, pour order 890): 21 vertices, not listed, extent 1926.38,249.06 2411,594.06
5V_IN on Bottom Layer "net" (solid, remove dead copper, pour order 892): 2413.32,593 2285.43,593 2269.77,608.65 2269.77,706.77 2329,766 2425,766 2440,751 2440,619.68
CB_PMIC_1V2 on Bottom Layer "NONET_L-01_P-001" (solid, remove dead copper, pour order 896): 23 vertices, not listed, extent 1699.37,2519.06 2167.37,4150.65
NetJ10_1 on Bottom Layer "Bottom Layer-No Net" (solid, pour order 900): 675,3295 675,3250 700,3225 810,3225 830,3245 830,3290 810,3310 690,3310
XDSET_1_VBUS on Bottom Layer "NONET_L-01_P-001" (solid, remove dead copper, pour order 902): 2449,3354 2440,3345 2375,3345 2368,3352 2368,3416.69 2390.37,3439.06 2436.37,3439.06 2449,3426.43
NetJ11_6 on Bottom Layer "NONET_L-01_P-001" (solid, remove dead copper, pour order 904): 18 vertices, not listed, extent 2523.48,3115.06 2755.91,3481.15
FTDI_VBUS on Bottom Layer "NONET_L-01_P-001" (solid, remove dead copper, pour order 906): 2349.37,4240.43 2349.37,4157.68 2367.99,4139.06 2534.37,4139.06 2554.37,4159.06 2554.37,4218.55 2520.07,4252.86 2362.34,4252.86 2349.92,4240.43
NetJ12_1 on Bottom Layer "NONET_L-01_P-001" (solid, remove dead copper, pour order 908): 2551.67,3993.06 2556.45,3997.83 2619.2,3997.83 2620.37,3999 2620.37,4011.06 2618.37,4013.06 2572.2,4013.05 2551.37,4033.89 2551.37,4075.06 2551.37,4125.06 2544.37,4132.06 2484.37,4132.06 2476.37,4124.06 2476.37,4036.43 2519.75,3993.06
MCU_5V on Bottom Layer "NONET_L-01_P-001" (solid, remove dead copper, pour order 910): 485.55,3612.07 494.07,3603.56 584.87,3603.56 629.37,3559.06 698.75,3559.06 698.75,3559.54 711.06,3571.86 711.06,3678.49 695.5,3694.06 506.55,3694.06 485.55,3673.06
NetJ11_1 on Bottom Layer "NONET_L-01_P-001" (solid, remove dead copper, pour order 912): 2524.44,3384.56 2503.11,3405.89 2474.89,3405.89 2466,3397 2466,3363 2511.63,3317.38 2518.27,3317.38 2620.43,3317.36 2630.93,3327.86 2630.93,3341.19 2622.7,3349.42 2559.58,3349.42
GND on Bottom Layer "GND_L01_P-001" (solid, remove dead copper, pour order 916): 35 vertices, not listed, extent 1781.65,1716.46 1937.65,2009.68
PMIC_1V8 on Bottom Layer "M1 Board Outline-No Net" (solid, pour order 930): 17 vertices, not listed, extent 1862.22,1555.84 2049.22,1712.46
PMIC_3V3 on Bottom Layer "M1 Board Outline-No Net" (solid, pour order 932): 1854.22,2404.84 1854.22,2477.84 1854.22,2483.84 1850.22,2487.84 1829.01,2509.06 1705.43,2509.06 1692.22,2495.84 1667.22,2470.84 1667.22,2397.84 1667.22,2357.84 1675.22,2349.84 1680.22,2344.84 1716.22,2344.84 1837.22,2344.84 1854.22,2361.84
PMIC_1V0 on Bottom Layer "M1 Board Outline-No Net" (solid, pour order 934): 19 vertices, not listed, extent 1652.22,1550.46 1847.22,1713.65
PMIC_1V2 on Bottom Layer "M1 Board Outline-No Net" (solid, pour order 936): 18 vertices, not listed, extent 1870.22,2352.46 2075.22,2499.46
WIDE_IN_5V_OP on Bottom Layer "NONET_L-01_P-001" (solid, remove dead copper, pour order 938): 21 vertices, not listed, extent 547,1067.06 751,1226
NetJ12_6 on Bottom Layer "NONET_L-01_P-001" (solid, remove dead copper, pour order 940): 25 vertices, not listed, extent 2492.37,3785.3 2743.37,4120.06
NetD1_1 on Bottom Layer "net" (solid, remove dead copper, pour order 942): 17 vertices, not listed, extent 2169.37,19.06 2569.37,319.06
GND on Bottom Layer "net" (solid, remove dead copper, pour order 944): 1919.37,25 1924.37,20 2265.31,20 2279.37,34.06 2279.37,84.06 2269.37,94.06 2164.37,94.06 2149.37,109.06 2149.37,206.1 2111.42,244.06 1944.37,244.05 1919.37,219.05
5V_IN on Bottom Layer "NONET_L-01_P-001" (solid, remove dead copper, pour order 946): 726.37,3439.06 719.37,3432.06 719.37,3339.47 730.26,3328.58 730.73,3329.06 818.37,3329.06 829.37,3340.06 829.37,3436.94 807.25,3459.06 746.94,3459.06 726.94,3439.06
5V_IN on Bottom Layer "NONET_L-01_P-001" (solid, remove dead copper, pour order 948): 877.84,3560 900,3582.16 910.58,3592.74 910,3647 910,3730 890,3750 826.37,3750 800,3723.63 800,3580 820,3560
NetJ17_1 on Bottom Layer "NONET_L-01_P-001" (solid, remove dead copper, pour order 952): 520.24,4610.13 520.24,4549.04 529.28,4540 627,4540 651,4564 651,4630 641,4640 531,4640 519.31,4628.31 519.31,4611.06
5V_IN on Bottom Layer "NONET_L-01_P-001" (solid, remove dead copper, pour order 954): 519.37,4492 519,4491.63 519,4432 531,4420 640,4420 656.37,4436.37 656.37,4478.18 640.55,4494 521,4494
5V_IN on Bottom Layer "M1 Board Outline-No Net" (solid, pour order 918): 33 vertices, not listed, extent 1893.96,2054.11 1996.96,2259.11
5V_IN on Bottom Layer "M1 Board Outline-No Net" (solid, pour order 920): 26 vertices, not listed, extent 1719.96,2054.11 1825.96,2259.11
BRD_3V3 on Bottom Layer "Bottom Layer-No Net 1" (solid, remove dead copper, pour order 1026): 887.89,2780.41 887.89,2713 877.85,2702.96 877.34,2679.49 881.77,2675.06 1015,2675.06 1029.06,2689.11 1029.06,2750 1024.06,2755 949.37,2755 918.92,2785.45 892.93,2785.45
VBOOST_5V on Bottom Layer "AVDD" (solid, pour order 926): 1116.62,1724.38 1128,1713 1192,1713 1199,1720 1199,1741.16 1184.62,1755.53 1184.62,1809.53 1169.62,1824.53 1126.62,1824.53 1116.62,1814.53
5V_IN on Bottom Layer "GND_L01_P-001" (solid, remove dead copper, pour order 928): 26 vertices, not listed, extent 1891.22,1799.32 2005.08,2001.46
VLDO_3V3 on Bottom Layer "NONET_L-01_P-001" (solid, pour order 898): 24 vertices, not listed, extent 949.37,2541.13 1379.37,2718.15
BOOST_3V3_IN on Bottom Layer "AVDD" (solid, pour order 894): 20 vertices, not listed, extent 950.55,1510 1077.62,1831
GND on Bottom Layer "BOTTOM-GND 7" (solid, pour order 950): 307 vertices, not listed, extent 1774.7,2054.6 1942.8,2333.1
FTDI_3V3 on L3-SIG1 "L06-PWR2-No Net" (solid, remove dead copper, pour order 962): 54 vertices, not listed, extent 1069.37,2542 1879.37,3819.06
CB_PMIC_1V0 on L3-SIG1 "NONET_L-01_P-001" (solid, remove dead copper, pour order 960): 27 vertices, not listed, extent 1539.37,1534 2714.37,3969.06
PMIC_1V0 on L3-SIG1 "NONET_L-01_P-001" (solid, remove dead copper, pour order 966): 1798.14,1529.82 1798.14,1491.29 1821.37,1468.06 1821.37,1435.06 1805.37,1419.06 1658.37,1419.06 1639.37,1438.06 1639.4,1438.08 1639.4,1469.03 1639.37,1469.06 1639.37,1669.06 1689.37,1719.06 1819.37,1719.06 1829.37,1709.06 1829.37,1561.06
VCC_XDS_3V3 on L3-SIG1 "NONET_L-01_P-001" (solid, remove dead copper, pour order 964): 72 vertices, not listed, extent 775,2425.8 1784.37,3934.06
UNREG_IN2 on L3-SIG1 "NONET_L-01_P-001" (solid, remove dead copper, pour order 956): 18 vertices, not listed, extent 880.17,689.06 2070.37,1109.06
UNREG_IN1 on L3-SIG1 "NONET_L-01_P-001" (solid, remove dead copper, pour order 958): 2089.37,680.37 2050,641 2050,476 2071,455 2315,455 2384,524 2384,1491 2285.94,1589.06 2066.37,1589.06 1993.37,1515.8 1993.37,1418.06 1869.37,1293.06 1869.37,1009.06 2087.64,790.79 2089.37,790.79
